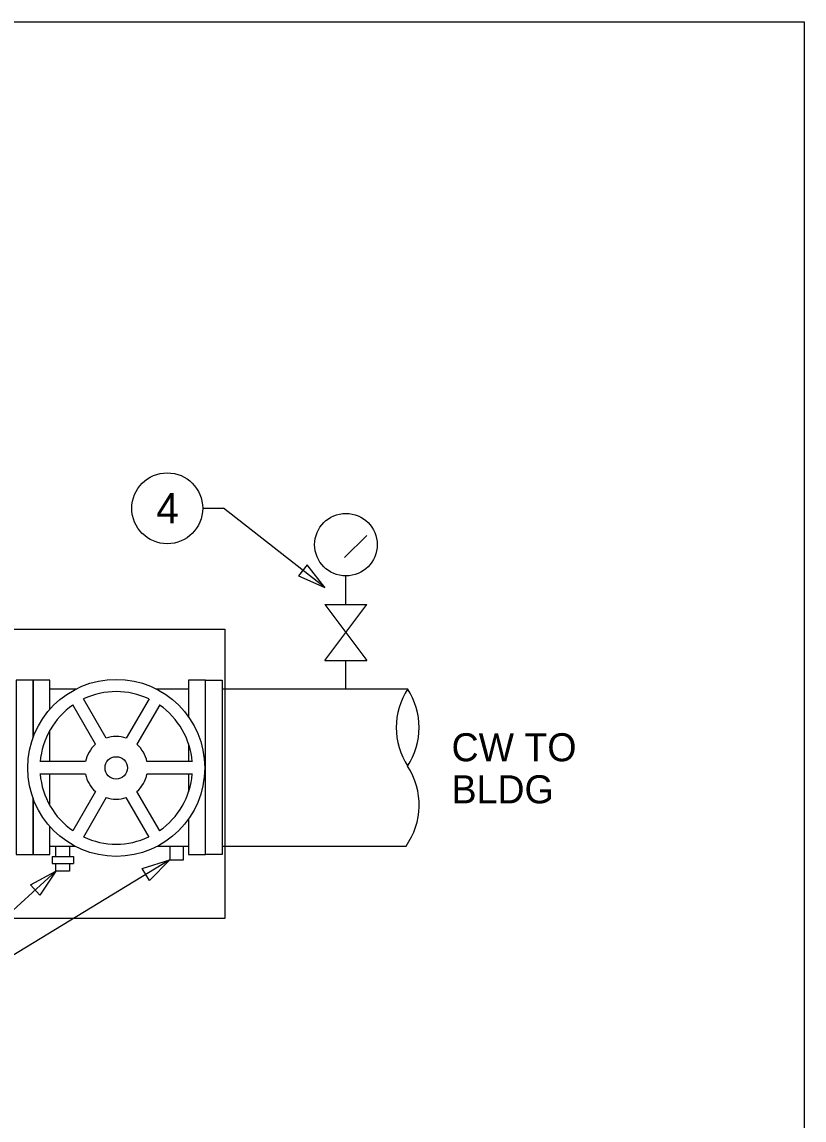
# Model space of a CAD drawing. Extents: x 10291.2 to 10382.2, y 10083.1 to 10135.3.
# Drawn here: x 10363.56 to 10382.16, y 10109.18 to 10135.29 of the extents above; entities that cross this region are included whole.
import ezdxf

# ---------------------------------------------------------------- set-up
doc = ezdxf.new("R2010")
doc.units = 0
for name, color, linetype in [('G-ANNO-NPLT', 7, 'Continuous'), ('G-ANNO-SYMB', 7, 'Continuous'), ('G-DETL-LINE', 7, 'Continuous'), ('G-DETL-TEXT', 7, 'Continuous')]:
    doc.layers.add(name, color=color, linetype=linetype)

msp = doc.modelspace()

# ---------------------------------------------------------------- linework, layer by layer
at = {"layer": 'G-ANNO-NPLT'}
msp.add_lwpolyline([(10336.657, 10086.15), (10336.657, 10135.292), (10382.157, 10135.292), (10382.157, 10086.15)], close=True, dxfattribs=at)
at = {"layer": 'G-ANNO-SYMB'}
msp.add_circle((10367.013, 10123.729), 0.843, dxfattribs=at)
at = {"layer": 'G-DETL-LINE'}
for p, q in [((10371.232, 10122.559), (10371.759, 10123.085)), ((10371.262, 10121.445), (10371.262, 10122.12)), ((10370.762, 10121.445), (10371.762, 10121.445)), ((10370.762, 10120.111), (10371.762, 10121.445)), ((10370.762, 10121.445), (10371.762, 10120.111)), ((10370.762, 10120.111), (10371.762, 10120.111)), ((10371.262, 10119.436), (10371.262, 10120.111)), ((10364.223, 10119.436), (10364.854, 10119.436)), ((10366.746, 10119.436), (10367.522, 10119.436)), ((10368.323, 10119.436), (10372.731, 10119.436)), ((10365.561, 10118.264), (10365.02, 10119.201)), ((10366.58, 10119.201), (10366.039, 10118.264)), ((10365.307, 10118.117), (10364.766, 10119.054)), ((10366.834, 10119.054), (10366.293, 10118.117)), ((10365.069, 10117.706), (10363.986, 10117.706)), ((10367.614, 10117.706), (10366.531, 10117.706)), ((10365.069, 10117.407), (10363.986, 10117.407)), ((10367.614, 10117.407), (10366.531, 10117.407)), ((10365.307, 10116.996), (10364.766, 10116.059)), ((10366.834, 10116.059), (10366.293, 10116.996)), ((10365.561, 10116.849), (10365.02, 10115.912)), ((10366.58, 10115.912), (10366.039, 10116.849)), ((10364.223, 10115.696), (10364.816, 10115.696)), ((10364.368, 10115.453), (10364.368, 10115.696)), ((10364.693, 10115.696), (10364.693, 10115.453)), ((10366.784, 10115.696), (10367.522, 10115.696)), ((10367.072, 10115.696), (10367.072, 10115.37)), ((10367.398, 10115.37), (10367.398, 10115.696)), ((10368.323, 10115.697), (10372.693, 10115.697)), ((10364.28, 10115.453), (10364.781, 10115.453)), ((10364.28, 10115.453), (10364.28, 10115.285)), ((10364.28, 10115.453), (10364.28, 10115.453)), ((10364.781, 10115.453), (10364.781, 10115.285)), ((10364.781, 10115.453), (10364.781, 10115.453)), ((10364.28, 10115.285), (10364.781, 10115.285)), ((10364.28, 10115.285), (10364.28, 10115.285)), ((10364.368, 10115.1), (10364.368, 10115.285)), ((10364.693, 10115.285), (10364.693, 10115.1)), ((10364.781, 10115.285), (10364.781, 10115.285)), ((10367.072, 10115.37), (10367.398, 10115.37)), ((10364.693, 10115.1), (10364.368, 10115.1))]:
    msp.add_line(p, q, dxfattribs=at)
for points in [[(10363.823, 10118.277), (10363.823, 10119.639), (10363.422, 10119.639), (10363.422, 10115.494), (10363.823, 10115.494), (10363.823, 10116.836)], [(10364.223, 10118.951), (10364.223, 10119.639), (10363.823, 10119.639), (10363.823, 10118.277)], [(10367.522, 10116.346), (10367.522, 10115.494), (10367.922, 10115.494), (10367.922, 10119.639), (10367.522, 10119.639), (10367.522, 10118.767)], [(10364.223, 10117.706), (10364.223, 10118.453)], [(10367.522, 10118.129), (10367.522, 10117.706)], [(10364.223, 10116.66), (10364.223, 10117.407)], [(10367.522, 10117.407), (10367.522, 10116.984)], [(10363.823, 10116.836), (10363.823, 10115.494), (10364.223, 10115.494), (10364.223, 10116.162)]]:
    msp.add_lwpolyline(points, dxfattribs=at)
msp.add_lwpolyline([(10367.922, 10119.639), (10368.323, 10119.639), (10368.323, 10115.494), (10367.922, 10115.494)], close=True, dxfattribs=at)
for centre, radius in [((10371.262, 10122.864), 0.744), ((10365.8, 10117.557), 2.105), ((10365.8, 10117.557), 0.265)]:
    msp.add_circle(centre, radius, dxfattribs=at)
for centre, radius, start, end in [((10365.8, 10117.557), 1.814, 64.6295, 115.3705), ((10374.15, 10118.516), 1.691, 147.0136, 212.9864), ((10371.312, 10118.516), 1.691, 327.0136, 32.9864), ((10365.8, 10117.557), 1.814, 124.6295, 175.2858), ((10365.8, 10117.557), 1.814, 4.7142, 55.3705), ((10365.8, 10117.557), 0.746, 71.3127, 108.6873), ((10365.8, 10117.557), 0.746, 131.3127, 168.4779), ((10365.8, 10117.557), 0.746, 11.5221, 48.6873), ((10371.312, 10116.674), 1.691, 324.6797, 32.9864), ((10365.8, 10117.557), 1.814, 184.7142, 235.3705), ((10365.8, 10117.557), 0.746, 191.5221, 228.6873), ((10365.8, 10117.557), 0.746, 311.3127, 348.4779), ((10365.8, 10117.557), 1.814, 304.6295, 355.2858), ((10365.8, 10117.557), 0.746, 251.3127, 288.6873), ((10365.8, 10117.557), 1.814, 244.6295, 295.3705)]:
    msp.add_arc(centre, radius, start, end, dxfattribs=at)
at = {"layer": 'G-DETL-TEXT'}
for p, q in [((10367.855, 10123.729), (10368.355, 10123.729)), ((10370.762, 10121.843), (10368.355, 10123.729)), ((10367.072, 10115.37), (10359.729, 10110.897)), ((10364.368, 10115.1), (10359.729, 10110.897))]:
    msp.add_line(p, q, dxfattribs=at)
for points in [[(10370.134, 10122.123), (10370.762, 10121.843), (10370.34, 10122.386)], [(10346.072, 10120.859), (10368.384, 10120.859), (10368.384, 10113.973), (10346.072, 10113.973)], [(10366.416, 10115.166), (10367.072, 10115.37), (10366.59, 10114.881)], [(10363.762, 10114.775), (10364.368, 10115.1), (10363.986, 10114.528)]]:
    msp.add_lwpolyline(points, close=True, dxfattribs=at)

# ---------------------------------------------------------------- texts
at = {"layer": 'G-ANNO-SYMB'}
msp.add_text('4', height=0.721, dxfattribs=at).set_placement((10366.754, 10123.368))
at = {"layer": 'G-DETL-TEXT'}
for s, p in [('CW TO', (10373.775, 10117.714)), ('BLDG', (10373.775, 10116.714))]:
    msp.add_text(s, height=0.6667, dxfattribs=at).set_placement(p)

doc.saveas('drawing.dxf')
